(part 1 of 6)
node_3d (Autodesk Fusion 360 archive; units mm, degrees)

design "body_model_corrections" references "pogo_bottomconnect pcb2_", "PCB_forkeypad1_redo", "PCB_forkeypad", "pogo_connect_with_wire", "button"
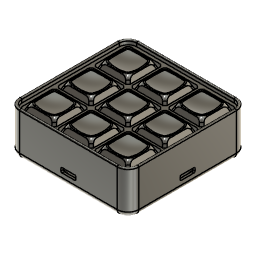
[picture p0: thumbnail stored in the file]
sketch "body" plane through (0, 0, 0) normal (0, 0, 1) x axis (1, 0, 0)
  line L1 (-44, 54) -> (44, 54)
  line L2 (-54, -44) -> (-54, 44)
  line L3 (44, -54) -> (-44, -54)
  line L4 (54, 44) -> (54, -44)
  line L5 (-54, -54) -> (54, 54)
  line L6 (54, -54) -> (-54, 54)
  line L7 (46, 47) -> (-46, 47)
  line L8 (47, -46) -> (47, 46)
  line L9 (-46, -47) -> (46, -47)
  line L10 (-47, 46) -> (-47, -46)
  line L11 (47, -47) -> (-47, 47)
  line L12 (-47, -47) -> (47, 47)
  line L13 (-47.5, 49) -> (47.5, 49)
  line L14 (-51.5, -45) -> (-51.5, 45)
  line L15 (47.5, -49) -> (-47.5, -49)
  line L16 (51.5, 49) -> (51.5, -45)
  line L17 (-51.5, -49) -> (51.5, 49)
  line L18 (51.5, -49) -> (-51.5, 49)
  line L19 (44, -52) -> (-44, -52)
  line L20 (52, 44) -> (52, -44)
  line L21 (-44, 52) -> (44, 52)
  line L22 (-52, -44) -> (-52, 44)
  line L23 (-52, 44) -> (-51.5, 44)
  line L24 (-44.2206, 52) -> (-44.2206, 49)
  line L25 (-51.5, 45) -> (-51.5, 44)
  line L26 (-47.5, 49) -> (-44.2206, 49)
  line L27 (-45, 55) -> (45, 55)
  line L28 (-55, -45) -> (-55, 45)
  line L29 (45, -55) -> (-45, -55)
  line L30 (55, 45) -> (55, -45)
  line L31 (-55, -55) -> (55, 55)
  line L32 (55, -55) -> (-55, 55)
  line L33 (-53, -45) -> (-53, 45)
  line L34 (45, -53) -> (-45, -53)
  line L35 (53, 45) -> (53, -45)
  line L36 (-45, 53) -> (45, 53)
  arc A1 centre (-47.5, 45) radius 4 clockwise from (-51.5, 45) to (-47.5, 49)
  arc A2 centre (47.5, 45) radius 4 clockwise from (47.5, 49) to (51.5, 45)
  arc A3 centre (-47.5, -45) radius 4 clockwise from (-47.5, -49) to (-51.5, -45)
  arc A4 centre (47.5, -45) radius 4 clockwise from (51.5, -45) to (47.5, -49)
  arc A5 centre (-44, 44) radius 10 clockwise from (-54, 44) to (-44, 54)
  arc A6 centre (44, 44) radius 10 clockwise from (44, 54) to (54, 44)
  arc A7 centre (-44, -44) radius 10 clockwise from (-44, -54) to (-54, -44)
  arc A8 centre (44, -44) radius 10 clockwise from (54, -44) to (44, -54)
  arc A9 centre (44, -44) radius 8 clockwise from (52, -44) to (44, -52)
  arc A10 centre (44, 44) radius 8 clockwise from (44, 52) to (52, 44)
  arc A11 centre (-44, 44) radius 8 clockwise from (-52, 44) to (-44, 52)
  arc A12 centre (-44, -44) radius 8 clockwise from (-44, -52) to (-52, -44)
  arc A13 centre (-46, 46) radius 1 clockwise from (-47, 46) to (-46, 47)
  arc A14 centre (46, 46) radius 1 clockwise from (46, 47) to (47, 46)
  arc A15 centre (-46, -46) radius 1 clockwise from (-46, -47) to (-47, -46)
  arc A16 centre (46, -46) radius 1 clockwise from (47, -46) to (46, -47)
  arc A17 centre (45, -45) radius 10 clockwise from (55, -45) to (45, -55)
  arc A18 centre (-45, -45) radius 10 clockwise from (-45, -55) to (-55, -45)
  arc A19 centre (-45, 45) radius 10 clockwise from (-55, 45) to (-45, 55)
  arc A20 centre (45, 45) radius 10 clockwise from (45, 55) to (55, 45)
  arc A21 centre (-45, -45) radius 8 clockwise from (-45, -53) to (-53, -45)
  arc A22 centre (45, -45) radius 8 clockwise from (53, -45) to (45, -53)
  arc A23 centre (45, 45) radius 8 clockwise from (45, 53) to (53, 45)
  arc A24 centre (-45, 45) radius 8 clockwise from (-53, 45) to (-45, 53)
  point P6 (0, 0)
  point P1 (0, 0)
  point P11 (0, 0)
  point P7 (-47, 47)
  point P16 (0, 0)
  point P13 (-51.5, 49)
  point P12 (51.5, 49)
  point P14 (-51.5, -49)
  point P15 (51.5, -49)
  point P3 (-54, 54)
  point P2 (54, 54)
  point P4 (-54, -54)
  point P5 (54, -54)
  point P8 (47, 47)
  point P10 (-47, -47)
  point P9 (47, -47)
  point P65 (-51.5, 44)
  point P66 (-52, 44)
  point P67 (-44.2206, 49)
  point P68 (-44.2206, 52)
  point P73 (0, 0)
  point P72 (55, -55)
  point P71 (-55, -55)
  point P70 (-55, 55)
  point P69 (55, 55)
  horizontal L1
  perpendicular L1 L2
  parallel L1 L3
  parallel L2 L4
  coincident L5 P6
  coincident L6 P6
  coincident P1 P6
  horizontal L7
  perpendicular L7 L8
  parallel L7 L9
  parallel L8 L10
  coincident L11 P11
  coincident L12 P11
  coincident L6 P7
  coincident P1 P11
  horizontal L13
  perpendicular L13 L14
  parallel L13 L15
  parallel L14 L16
  coincident L17 P16
  coincident L18 P16
  coincident P11 P16
  coincident P13 L13
  coincident P13 L14
  tangent L13 A1
  tangent L14 A1
  coincident P12 L13
  tangent L13 A2
  equal A1 A2
  coincident P14 L15
  coincident P14 L14
  tangent L15 A3
  tangent L14 A3
  equal A1 A3
  coincident P15 L15
  coincident P15 L16
  tangent L15 A4
  tangent L16 A4
  coincident P3 L2
  coincident P3 L1
  tangent L2 A5
  tangent L1 A5
  coincident P2 L1
  coincident P2 L4
  tangent L1 A6
  tangent L4 A6
  equal A5 A6
  coincident P4 L3
  coincident P4 L2
  tangent L3 A7
  tangent L2 A7
  equal A5 A7
  coincident P5 L4
  coincident P5 L3
  tangent L4 A8
  tangent L3 A8
  equal A5 A8
  coincident P7 L10
  coincident P7 L7
  tangent L10 A13
  tangent L7 A13
  coincident P8 L7
  coincident P8 L8
  tangent L7 A14
  tangent L8 A14
  equal A13 A14
  coincident P10 L10
  coincident P10 L9
  tangent L10 A15
  tangent L9 A15
  equal A13 A15
  coincident P9 L8
  coincident P9 L9
  tangent L8 A16
  tangent L9 A16
  equal A13 A16
  coincident L14 P65
  coincident L22 P66
  perpendicular L22 L23
  coincident L13 P67
  coincident L21 P68
  perpendicular L21 L24
  horizontal L27
  perpendicular L27 L28
  parallel L27 L29
  parallel L28 L30
  coincident L31 P73
  coincident L32 P73
  coincident P16 P73
  coincident P72 L30
  coincident P72 L29
  tangent L30 A17
  tangent L29 A17
  coincident P71 L28
  coincident P71 L29
  tangent L28 A18
  tangent L29 A18
  equal A17 A18
  coincident P70 L27
  coincident P70 L28
  tangent L27 A19
  tangent L28 A19
  equal A17 A19
  coincident P69 L30
  coincident P69 L27
  tangent L30 A20
  tangent L27 A20
  equal A17 A20
  dimension "d1" distance P4 P5 = 108
  dimension "d2" distance P3 P4 = 108
  dimension "d3" = -2
  dimension "d22" distance P14 P15 = 103
  dimension "d23" distance P13 P14 = 98
  dimension "d24" radius A1 = 4
  dimension "d25" radius A4 = 4
  dimension "d26" radius A5 = 10
  dimension "d40" radius A13 = 1
  dimension "d355" distance P71 P72 = 110
  dimension "d356" distance P70 P71 = 110
  dimension "d357" radius A17 = 10
  dimension "d358" = -2
sketch "Sketch2" plane through (0, 0, 0) normal (0, 0, 1) x axis (1, 0, 0)
  line L1 (0, 0) -> (0, 54)
  line L2 (-15, -87.1142) -> (-15, 54)
  line L3 (15, -87.1142) -> (15, 54)
  line L4 (-15, 49) -> (15, 49)
  line L5 (-15, 45) -> (-15, 49)
  line L6 (15, 45) -> (-15, 45)
  line L7 (15, 49) -> (15, 45)
  line L8 (-15, 45) -> (15, 49)
  line L9 (15, 45) -> (-15, 49)
  line L10 (-22, 52) -> (-22, 47)
  line L11 (15, 49) -> (-15, 49)
  line L12 (-15, 47) -> (-15, 49)
  point P1 (0, 0)
  point P3 (0, 0)
  point P4 (-15, 54)
  point P6 (15, 54)
  point P5 (-15, -87.1142)
  point P7 (15, -87.1142)
  point P12 (0, 47)
  point P15 (-15, 47)
  point P10 (-15, 45)
  point P11 (15, 45)
  point P9 (-15, 49)
  coincident P1 P3
  vertical L1
  symmetric L1 P4 P6
  symmetric L1 P5 P7
  horizontal L4
  perpendicular L4 L5
  parallel L4 L6
  parallel L5 L7
  coincident L8 P12
  coincident L9 P12
  coincident L1 P12
  parallel L5 L10
  midpoint L5 P15
  dimension "d7" = 15
  dimension "d8" distance P10 P11 = 30
  dimension "d9" distance P9 P10 = 4
  dimension "d11" distance L2 L10 = 7
sketch "keyplate" plane through (0, 0, 0) normal (0, 0, 1) x axis (1, 0, 0)
  line L1 (-20, 50) -> (-48, 50)
  line L2 (-18, 20) -> (-18, 48)
  line L3 (-48, 18) -> (-20, 18)
  line L4 (-50, 48) -> (-50, 20)
  line L5 (-44, 52) -> (44, 52)
  line L6 (-52, -44) -> (-52, 44)
  line L7 (44.75, 51.75) -> (-44.75, 51.75)
  line L8 (51.75, -44.75) -> (51.75, 44.75)
  line L9 (-44.75, -51.75) -> (44.75, -51.75)
  line L10 (-51.75, 44.75) -> (-51.75, -44.75)
  line L11 (51.75, -51.75) -> (-51.75, 51.75)
  line L12 (-51.75, -51.75) -> (51.75, 51.75)
  line L13 (-50, 48) -> (-48, 50)
  line L14 (-20, 50) -> (-18, 48)
  line L15 (-20, 18) -> (-18, 20)
  line L16 (-50, 20) -> (-48, 18)
  line L17 (-14, 18) -> (14, 18)
  line L18 (-16, 20) -> (-14, 18)
  line L19 (-16, 48) -> (-16, 20)
  line L20 (-16, 48) -> (-14, 50)
  line L21 (14, 50) -> (-14, 50)
  line L22 (14, 50) -> (16, 48)
  line L23 (14, 18) -> (16, 20)
  line L24 (16, 20) -> (16, 48)
  line L25 (20, 18) -> (48, 18)
  line L26 (18, 20) -> (20, 18)
  line L27 (18, 48) -> (18, 20)
  line L28 (18, 48) -> (20, 50)
  line L29 (48, 50) -> (20, 50)
  line L30 (48, 50) -> (50, 48)
  line L31 (48, 18) -> (50, 20)
  line L32 (50, 20) -> (50, 48)
  line L33 (-48, -16) -> (-20, -16)
  line L34 (-50, -14) -> (-48, -16)
  line L35 (-50, 14) -> (-50, -14)
  line L36 (-50, 14) -> (-48, 16)
  line L37 (-20, 16) -> (-48, 16)
  line L38 (-20, 16) -> (-18, 14)
  line L39 (-20, -16) -> (-18, -14)
  line L40 (-18, -14) -> (-18, 14)
  line L41 (-14, -16) -> (14, -16)
  line L42 (-16, -14) -> (-14, -16)
  line L43 (-16, 14) -> (-16, -14)
  line L44 (-16, 14) -> (-14, 16)
  line L45 (14, 16) -> (-14, 16)
  line L46 (14, 16) -> (16, 14)
  line L47 (14, -16) -> (16, -14)
  line L48 (16, -14) -> (16, 14)
  line L49 (20, -16) -> (48, -16)
  line L50 (18, -14) -> (20, -16)
  line L51 (18, 14) -> (18, -14)
  line L52 (18, 14) -> (20, 16)
  line L53 (48, 16) -> (20, 16)
  line L54 (48, 16) -> (50, 14)
  line L55 (48, -16) -> (50, -14)
  line L56 (50, -14) -> (50, 14)
  line L57 (-48, -50) -> (-20, -50)
  line L58 (-50, -48) -> (-48, -50)
  line L59 (-50, -20) -> (-50, -48)
  line L60 (-50, -20) -> (-48, -18)
  line L61 (-20, -18) -> (-48, -18)
  line L62 (-20, -18) -> (-18, -20)
  line L63 (-20, -50) -> (-18, -48)
  line L64 (-18, -48) -> (-18, -20)
  line L65 (-14, -50) -> (14, -50)
  line L66 (-16, -48) -> (-14, -50)
  line L67 (-16, -20) -> (-16, -48)
  line L68 (-16, -20) -> (-14, -18)
  line L69 (14, -18) -> (-14, -18)
  line L70 (14, -18) -> (16, -20)
  line L71 (14, -50) -> (16, -48)
  line L72 (16, -48) -> (16, -20)
  line L73 (20, -50) -> (48, -50)
  line L74 (18, -48) -> (20, -50)
  line L75 (18, -20) -> (18, -48)
  line L76 (18, -20) -> (20, -18)
  line L77 (48, -18) -> (20, -18)
  line L78 (48, -18) -> (50, -20)
  line L79 (48, -50) -> (50, -48)
  line L80 (50, -48) -> (50, -20)
  line L81 (-16, 20) -> (-18, 20)
  line L82 (-16, 14) -> (-18, 14)
  line L83 (18, 20) -> (16, 20)
  line L84 (18, 14) -> (16, 14)
  line L85 (48, 16) -> (48, 18)
  line L86 (-48, 16) -> (-48, 18)
  line L87 (-48, -16) -> (-48, -18)
  line L88 (-18, -14) -> (-16, -14)
  line L89 (-18, -20) -> (-16, -20)
  line L90 (18, -14) -> (16, -14)
  line L91 (18, -20) -> (16, -20)
  line L92 (48, -18) -> (48, -16)
  line L93 (-44.75, -50) -> (-44.75, -51.75)
  line L94 (44.75, -50) -> (44.75, -51.75)
  line L95 (44.75, 50) -> (44.75, 51.75)
  line L96 (-44.75, 50) -> (-44.75, 51.75)
  line L97 (-14, -50) -> (-20, -50)
  line L98 (20, -50) -> (14, -50)
  line L99 (-14, 50) -> (-20, 50)
  line L100 (20, 50) -> (14, 50)
  line L101 (18, -32) -> (16, -32)
  line L102 (13.5, -32) -> (17, -32)
  line L103 (20.5, -32) -> (17, -32)
  line L104 (13.5, 50) -> (13.5, -50)
  line L105 (20.5, 50) -> (20.5, -50)
  line L106 (0, -4) -> (0, 0)
  line L107 (-20.5, 50) -> (-20.5, -50)
  line L108 (-13.5, 50) -> (-13.5, -50)
  line L109 (-44.75, -52.95) -> (44.75, -52.95)
  line L110 (52.95, -44.75) -> (52.95, 44.75)
  line L111 (44.75, 52.95) -> (-44.75, 52.95)
  line L112 (-52.95, 44.75) -> (-52.95, -44.75)
  arc A1 centre (-44.75, 44.75) radius 7 clockwise from (-51.75, 44.75) to (-44.75, 51.75)
  arc A2 centre (44.75, 44.75) radius 7 clockwise from (44.75, 51.75) to (51.75, 44.75)
  arc A3 centre (44.75, -44.75) radius 7 clockwise from (51.75, -44.75) to (44.75, -51.75)
  arc A4 centre (-44.75, -44.75) radius 7 clockwise from (-44.75, -51.75) to (-51.75, -44.75)
  arc A5 centre (-44.75, -44.75) radius 8.2 clockwise from (-44.75, -52.95) to (-52.95, -44.75)
  arc A6 centre (44.75, -44.75) radius 8.2 clockwise from (52.95, -44.75) to (44.75, -52.95)
  arc A7 centre (44.75, 44.75) radius 8.2 clockwise from (44.75, 52.95) to (52.95, 44.75)
  arc A8 centre (-44.75, 44.75) radius 8.2 clockwise from (-52.95, 44.75) to (-44.75, 52.95)
  point P13 (0, 0)
  point P1 (0, 0)
  point P9 (-51.75, 51.75)
  point P10 (51.75, 51.75)
  point P11 (51.75, -51.75)
  point P12 (-51.75, -51.75)
  point P2 (-50, 50)
  point P3 (-18, 50)
  point P4 (-18, 18)
  point P5 (-50, 18)
  point P99 (-44.75, -50)
  point P100 (44.75, -50)
  point P101 (44.75, 50)
  point P102 (-44.75, 50)
  point P103 (16, -32)
  point P104 (18, -32)
  point P105 (17, -32)
  point P108 (13.5, 50)
  point P106 (13.5, -32)
  point P110 (20.5, 50)
  point P107 (20.5, -32)
  point P112 (0, 0)
  point P117 (-13.5, 50)
  point P109 (13.5, -50)
  point P116 (-13.5, -50)
  point P115 (-20.5, 50)
  point P111 (20.5, -50)
  point P114 (-20.5, -50)
  point P27 (-48, 50)
  point P28 (-50, 48)
  point P29 (-18, 48)
  point P30 (-20, 50)
  point P31 (-18, 20)
  point P32 (-20, 18)
  point P33 (-48, 18)
  point P34 (-50, 20)
  horizontal L1
  vertical L2
  horizontal L3
  vertical L4
  horizontal L7
  perpendicular L7 L8
  parallel L7 L9
  parallel L8 L10
  coincident L11 P13
  coincident L12 P13
  coincident P1 P13
  coincident P9 L7
  coincident P9 L10
  tangent L7 A1
  tangent L10 A1
  coincident P10 L7
  coincident P10 L8
  tangent L7 A2
  tangent L8 A2
  equal A1 A2
  coincident P11 L9
  coincident P11 L8
  tangent L9 A3
  tangent L8 A3
  equal A1 A3
  coincident P12 L9
  coincident P12 L10
  tangent L9 A4
  tangent L10 A4
  equal A1 A4
  coincident P2 L1
  coincident P2 L4
  coincident P3 L2
  coincident P3 L1
  coincident P4 L2
  coincident P4 L3
  coincident P5 L3
  coincident P5 L4
  coincident L57 P99
  perpendicular L57 L93
  coincident L73 P100
  perpendicular L73 L94
  coincident L29 P101
  perpendicular L29 L95
  coincident L1 P102
  perpendicular L1 L96
  coincident L72 P103
  coincident L75 P104
  perpendicular L75 L101
  midpoint L101 P105
  perpendicular L75 L102
  perpendicular L75 L103
  coincident L21 P108
  perpendicular L21 L104
  coincident P106 L104
  coincident L29 P110
  perpendicular L29 L105
  coincident P107 L105
  coincident P1 P112
  perpendicular L41 L106
  symmetric P108 L106 P117
  symmetric P109 L106 P116
  symmetric P110 L106 P115
  symmetric P111 L106 P114
  dimension "d12" distance P2 P3 = 32
  dimension "d13" distance P2 P5 = 32
  dimension "d14" distance L1 L5 = 2
  dimension "d15" distance L4 L6 = 2
  dimension "d20" distance P11 P12 = 103.5
  dimension "d21" distance P10 P11 = 103.5
  dimension "d27" radius A1 = 7
  dimension "d28" distance P2 P27 = 2
  dimension "d29" distance P2 P28 = 2 (= "d28")
  dimension "d30" distance P3 P29 = 2
  dimension "d31" distance P3 P30 = 2 (= "d30")
  dimension "d32" distance P4 P31 = 2
  dimension "d33" distance P4 P32 = 2 (= "d32")
  dimension "d34" distance P5 P33 = 2
  dimension "d35" distance P5 P34 = 2 (= "d34")
  dimension "d266" distance P105 P106 = 3.5
  dimension "d267" distance P105 P107 = 3.5
  dimension "d364" = -1.2
  dimension "d38" R-Pattern1-uDistance = 34
  dimension "d39" R-Pattern1-vDistance = -34
sketch "slot" plane through (0, 0, 0) normal (0, 0, 1) x axis (1, 0, 0)
  line L1 (0, 54) -> (0, 0)
  line L2 (20, 54) -> (20, 0)
  line L3 (-20, 54) -> (-20, 0)
  line L4 (20, 49) -> (-20, 49)
  line L5 (-15, 49) -> (-15, 47)
  line L6 (15, 49) -> (15, 47)
  line L7 (-22, 47) -> (-15, 47)
  line L8 (22, 47) -> (15, 47)
  line L9 (-20, 52) -> (-20, 49)
  line L10 (20, 52) -> (20, 49)
  line L11 (20, 52) -> (20, 49)
  line L12 (-3.25, 49) -> (-3.25, 50.9)
  line L13 (3.25, 49) -> (3.25, 50.9)
  line L14 (-22, 47) -> (-22, 52)
  line L15 (22, 47) -> (22, 52)
  line L16 (22, 52) -> (-22, 52)
  line L17 (15, 47) -> (-15, 47)
  line L18 (-3.25, 50.9) -> (3.25, 50.9)
  line L19 (22, 50.9) -> (3.25, 50.9)
  line L20 (-22, 50.9) -> (-3.25, 50.9)
  line L21 (-15, 49.5) -> (-15, 49)
  point P8 (-20, 49)
  point P9 (20, 49)
  point P11 (-15, 49)
  point P13 (15, 49)
  point P14 (-20, 52)
  point P15 (20, 52)
  point P16 (20, 49)
  point P18 (-3.25, 49)
  point P20 (3.25, 49)
  point P25 (22, 50.9)
  point P26 (-22, 50.9)
  point P17 (-3.25, 50.9)
  point P19 (3.25, 50.9)
  vertical L1
  coincident L3 P8
  coincident L2 P9
  perpendicular L2 L4
  coincident L4 P11
  perpendicular L4 L5
  coincident L4 P13
  perpendicular L4 L6
  horizontal L7
  coincident L3 P14
  coincident L2 P15
  symmetric L1 P8 P16
  symmetric L1 P14 P15
  coincident L4 P18
  coincident L4 P20
  perpendicular L7 L14
  perpendicular L8 L15
  perpendicular L15 L16
  perpendicular L6 L17
  coincident L15 P25
  perpendicular L15 L19
  coincident L14 P26
  perpendicular L14 L20
  perpendicular L4 L21
  dimension "d48" distance L1 L5 = 15
  dimension "d49" distance L1 L6 = 15
  dimension "d50" distance L1 L9 = 20
  dimension "d51" distance L1 L10 = 20
  dimension "d52" distance P8 P14 = 3
  dimension "d55" distance L1 L12 = 3.25
  dimension "d56" distance L1 L13 = 3.25
  dimension "d57" distance P17 P18 = 1.9
  dimension "d58" distance P19 P20 = 1.9
  dimension "d63" distance L9 L14 = 2
  dimension "d64" distance L10 L15 = 2
extrude "Extrude7" new body sketch "body" profile of L1 L2 L3 L4 L22 L19 L20 L21 L7 L8 L9 L10 A1 A5 A11 A6 A10 A7 A12 A8 A9 A13 A14 A15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 against normal blind 28
shell "Shell2" innerThickness 2
extrude "Extrude8" sketch "body" profile of L22 L19 L20 L21 L7 L8 L9 L10 A1 A11 A10 A12 A9 A13 A14 A15 A16 L23 L24 L25 L26 L34 A22 L36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 blind 19.2
fillet "Fillet2" radius 5
extrude "Extrude15" cut sketch "slot" profile of L4 L5 L6 L9 L10 L11 L12 L13 L17 L18 L19 L20 against normal blind 26
extrude "Extrude16" sketch "slot" profile of L4 L9 L10 L11 L12 L13 L19 L20 blind 3.5
sketch "holder" plane through (0, 0, 0) normal (0, 0, 1) x axis (1, 0, 0)
  line L1 (12, 16) -> (-12, 16)
  line L2 (16, -12) -> (16, 12)
  line L3 (-12, -16) -> (12, -16)
  line L4 (-16, 12) -> (-16, -12)
  line L5 (16, -16) -> (-16, 16)
  line L6 (-16, -16) -> (16, 16)
  line L7 (-12, -16.15) -> (12, -16.15)
  line L8 (16.15, -12) -> (16.15, 12)
  line L9 (12, 16.15) -> (-12, 16.15)
  line L10 (-16.15, 12) -> (-16.15, -12)
  line L11 (-12, -17.8) -> (12, -17.8)
  line L12 (17.8, -12) -> (17.8, 12)
  line L13 (12, 17.8) -> (-12, 17.8)
  line L14 (-17.8, 12) -> (-17.8, -12)
  line L15 (-12, -14.65) -> (12, -14.65)
  line L16 (14.65, -12) -> (14.65, 12)
  line L17 (12, 14.65) -> (-12, 14.65)
  line L18 (-14.65, 12) -> (-14.65, -12)
  line L19 (0, -14.65) -> (0, -17.8)
  line L20 (3.25, -14.65) -> (3.25, -17.8)
  line L21 (-3.25, -14.65) -> (-3.25, -17.8)
  line L22 (14.65, -3.25) -> (17.8, -3.25)
  line L23 (14.65, 3.25) -> (17.8, 3.25)
  line L24 (3.25, 14.65) -> (3.25, 17.8)
  line L25 (-3.25, 14.65) -> (-3.25, 17.8)
  line L26 (-14.65, 3.25) -> (-17.8, 3.25)
  line L27 (-14.65, -3.25) -> (-17.8, -3.25)
  line L28 (45, 53) -> (-45, 53)
  line L29 (53, -45) -> (53, 45)
  line L30 (-45, -53) -> (45, -53)
  line L31 (-53, 45) -> (-53, -45)
  line L32 (-45, 55) -> (45, 55)
  line L33 (-55, -45) -> (-55, 45)
  line L34 (45, -55) -> (-45, -55)
  line L35 (55, 45) -> (55, -45)
  arc A1 centre (12, 12) radius 4 clockwise from (12, 16) to (16, 12)
  arc A2 centre (-12, 12) radius 4 clockwise from (-16, 12) to (-12, 16)
  arc A3 centre (-12, -12) radius 4 clockwise from (-12, -16) to (-16, -12)
  arc A4 centre (12, -12) radius 4 clockwise from (16, -12) to (12, -16)
  arc A5 centre (-12, -12) radius 4.15 clockwise from (-12, -16.15) to (-16.15, -12)
  arc A6 centre (12, -12) radius 4.15 clockwise from (16.15, -12) to (12, -16.15)
  arc A7 centre (12, 12) radius 4.15 clockwise from (12, 16.15) to (16.15, 12)
  arc A8 centre (-12, 12) radius 4.15 clockwise from (-16.15, 12) to (-12, 16.15)
  arc A9 centre (-12, -12) radius 5.8 clockwise from (-12, -17.8) to (-17.8, -12)
  arc A10 centre (12, -12) radius 5.8 clockwise from (17.8, -12) to (12, -17.8)
  arc A11 centre (12, 12) radius 5.8 clockwise from (12, 17.8) to (17.8, 12)
  arc A12 centre (-12, 12) radius 5.8 clockwise from (-17.8, 12) to (-12, 17.8)
  arc A13 centre (-12, -12) radius 2.65 clockwise from (-12, -14.65) to (-14.65, -12)
  arc A14 centre (12, -12) radius 2.65 clockwise from (14.65, -12) to (12, -14.65)
  arc A15 centre (12, 12) radius 2.65 clockwise from (12, 14.65) to (14.65, 12)
  arc A16 centre (-12, 12) radius 2.65 clockwise from (-14.65, 12) to (-12, 14.65)
  arc A17 centre (45, 45) radius 8 clockwise from (45, 53) to (53, 45)
  arc A18 centre (45, -45) radius 8 clockwise from (53, -45) to (45, -53)
  arc A19 centre (-45, -45) radius 8 clockwise from (-45, -53) to (-53, -45)
  arc A20 centre (-45, 45) radius 8 clockwise from (-53, 45) to (-45, 53)
  arc A21 centre (45, 45) radius 10 clockwise from (45, 55) to (55, 45)
  arc A22 centre (-45, 45) radius 10 clockwise from (-55, 45) to (-45, 55)
  arc A23 centre (-45, -45) radius 10 clockwise from (-45, -55) to (-55, -45)
  arc A24 centre (45, -45) radius 10 clockwise from (55, -45) to (45, -55)
  point P6 (0, 0)
  point P1 (0, 0)
  point P3 (16, 16)
  point P2 (-16, 16)
  point P5 (-16, -16)
  point P4 (16, -16)
  point P55 (0, -17.8)
  point P56 (0, -14.65)
  horizontal L1
  perpendicular L1 L2
  parallel L1 L3
  parallel L2 L4
  coincident L5 P6
  coincident L6 P6
  coincident P1 P6
  coincident P3 L2
  coincident P3 L1
  tangent L2 A1
  tangent L1 A1
  coincident P2 L4
  coincident P2 L1
  tangent L4 A2
  tangent L1 A2
  coincident P5 L3
  coincident P5 L4
  tangent L3 A3
  tangent L4 A3
  equal A2 A3
  coincident P4 L3
  coincident P4 L2
  tangent L3 A4
  tangent L2 A4
  equal A2 A4
  concentric A3 A5
  concentric A4 A6
  concentric A1 A7
  concentric A2 A8
  tangent A5 L10
  tangent L8 A7
  tangent A5 L7
  tangent A6 L8
  tangent L7 A6
  tangent L9 A8
  tangent A7 L9
  tangent A8 L10
  midpoint L11 P55
  midpoint L15 P56
  perpendicular L15 L19
  dimension "d101" distance P4 P5 = 32
  dimension "d102" distance P3 P4 = 32
  dimension "d103" radius A1 = 4
  dimension "d104" radius A2 = 4
  dimension "d106" = -1.65
  dimension "d107" = 1.35
  dimension "d134" = 3.25
  dimension "d135" = -3.25
  dimension "d137" C-Pattern1-Angle = 360
sketch "close" plane through (0, 0, 0) normal (0, 1, 0) x axis (1, 0, 0)
  line L1 (3.25, 22.5) -> (3.25, 26)
  line L2 (20, 22.5) -> (3.25, 22.5)
  line L3 (20, 6.8) -> (20, 22.5)
  line L4 (-20, 6.8) -> (20, 6.8)
  line L5 (-20, 22.5) -> (-20, 6.8)
  line L6 (-3.25, 22.5) -> (-20, 22.5)
  line L7 (-3.25, 26) -> (-3.25, 22.5)
  line L8 (3.25, 26) -> (-3.25, 26)
  line L9 (-3, 17.75) -> (3, 17.75)
  line L10 (-6, 13.25) -> (-6, 14.75)
  line L11 (3, 10.25) -> (-3, 10.25)
  line L12 (6, 14.75) -> (6, 13.25)
  line L13 (-6, 10.25) -> (6, 17.75)
  line L14 (6, 10.25) -> (-6, 17.75)
  arc A1 centre (-3, 13.25) radius 3 clockwise from (-3, 10.25) to (-6, 13.25)
  arc A2 centre (-3, 14.75) radius 3 clockwise from (-6, 14.75) to (-3, 17.75)
  arc A3 centre (3, 14.75) radius 3 clockwise from (3, 17.75) to (6, 14.75)
  arc A4 centre (3, 13.25) radius 3 clockwise from (6, 13.25) to (3, 10.25)
  point P14 (0, 14)
  point P12 (-6, 10.25)
  point P11 (-6, 17.75)
  point P10 (6, 17.75)
  point P13 (6, 10.25)
  horizontal L9
  perpendicular L9 L10
  parallel L9 L11
  parallel L10 L12
  coincident L13 P14
  coincident L14 P14
  coincident P12 L11
  coincident P12 L10
  tangent L11 A1
  tangent L10 A1
  coincident P11 L10
  coincident P11 L9
  tangent L10 A2
  tangent L9 A2
  equal A1 A2
  coincident P10 L9
  coincident P10 L12
  tangent L9 A3
  tangent L12 A3
  equal A1 A3
  coincident P13 L12
  coincident P13 L11
  tangent L12 A4
  tangent L11 A4
  equal A1 A4
  dimension "d249" distance P10 P13 = 7.5
  dimension "d250" distance P10 P11 = 12
  dimension "d251" radius A1 = 3
extrude "Extrude17" sketch "close" profile of L1 L2 L3 L4 L5 L6 L7 L8 to an object bodies "close"
combine "Combine2"
offset_faces "OffsetFaces5" distance -0.15
offset_faces "OffsetFaces6" distance -0.15
offset_faces "OffsetFaces7" distance -0.15
offset_faces "OffsetFaces8" distance 0.15
offset_faces "OffsetFaces9" distance -1
offset_faces "OffsetFaces10" distance 0.2
offset_faces "OffsetFaces24" distance -0.15
sketch "pogpslot" plane through (0, 50.9, 0) normal (0, -1, 0) x axis (1, 0, 0)
  line L1 (3.25, -22.5) -> (3.25, -26)
  line L2 (20, -22.5) -> (3.25, -22.5)
  line L3 (20, -6.8) -> (20, -22.5)
  line L4 (-20, -6.8) -> (20, -6.8)
  line L5 (-20, -22.5) -> (-20, -6.8)
  line L6 (-3.25, -22.5) -> (-20, -22.5)
  line L7 (-3.25, -26) -> (-3.25, -22.5)
  line L8 (3.25, -26) -> (-3.25, -26)
  line L9 (15, -22.5) -> (3.25, -22.5)
  line L10 (-3.25, -22.5) -> (-15, -22.5)
  line L11 (0, -26) -> (0, -6.8)
  line L12 (20, -22) -> (-20, -22)
  line L13 (-15, -27.8) -> (-15, -6.8)
  line L14 (10, -22) -> (-10, -22)
  line L15 (-10, -12) -> (10, -12)
  line L16 (-5.92, -19.19) -> (5.92, -19.19)
  line L17 (-6.92, -15.81) -> (-6.92, -18.19)
  line L18 (5.92, -14.81) -> (-5.92, -14.81)
  line L19 (6.92, -18.19) -> (6.92, -15.81)
  line L20 (-6.92, -14.81) -> (6.92, -19.19)
  line L21 (6.92, -14.81) -> (-6.92, -19.19)
  arc A1 centre (10, -17) radius 5 clockwise from (10, -12) to (15, -17)
  arc A2 centre (10, -17) radius 5 clockwise from (15, -17) to (10, -22)
  arc A3 centre (-10, -17) radius 5 clockwise from (-15, -17) to (-10, -12)
  arc A4 centre (-10, -17) radius 5 clockwise from (-10, -22) to (-15, -17)
  arc A5 centre (-5.92, -15.81) radius 1 clockwise from (-6.92, -15.81) to (-5.92, -14.81)
  arc A6 centre (-5.92, -18.19) radius 1 clockwise from (-5.92, -19.19) to (-6.92, -18.19)
  arc A7 centre (5.92, -18.19) radius 1 clockwise from (6.92, -18.19) to (5.92, -19.19)
  arc A8 centre (5.92, -15.81) radius 1 clockwise from (5.92, -14.81) to (6.92, -15.81)
  point P14 (0, -6.8)
  point P15 (0, -26)
  point P16 (-20, -22)
  point P17 (20, -22)
  point P18 (-15, -6.8)
  point P20 (-15, -22)
  point P21 (15, -22)
  point P24 (15, -17)
  point P26 (15, -17)
  point P22 (-15, -12)
  point P30 (-15, -17)
  point P33 (-15, -17)
  point P39 (0, -17)
  point P37 (-6.92, -14.81)
  point P36 (-6.92, -19.19)
  point P35 (6.92, -19.19)
  point P38 (6.92, -14.81)
  midpoint L4 P14
  midpoint L8 P15
  coincident L5 P16
  coincident L3 P17
  perpendicular L3 L12
  coincident L4 P18
  perpendicular L4 L13
  horizontal L14
  horizontal L15
  coincident L13 P20
  coincident L12 P20
  tangent L15 A1
  coincident P21 L14
  tangent L14 A2
  equal A1 A2
  coincident P24 P26
  coincident P22 L15
  tangent L15 A3
  equal A1 A3
  coincident P20 L14
  tangent L14 A4
  equal A1 A4
  coincident P30 P33
  horizontal L16
  perpendicular L16 L17
  parallel L16 L18
  parallel L17 L19
  coincident L20 P39
  coincident L21 P39
  coincident L11 P39
  coincident P37 L17
  coincident P37 L18
  tangent L17 A5
  tangent L18 A5
  coincident P36 L17
  coincident P36 L16
  tangent L17 A6
  tangent L16 A6
  equal A5 A6
  coincident P35 L16
  coincident P35 L19
  tangent L16 A7
  tangent L19 A7
  equal A5 A7
  coincident P38 L18
  coincident P38 L19
  tangent L18 A8
  tangent L19 A8
  dimension "d138" distance L6 L12 = 0.5
  dimension "d139" distance L11 L13 = 15
  dimension "d140" distance P20 P21 = 30
  dimension "d142" radius A1 = 5
  dimension "d143" distance L14 L15 = 10
  dimension "d144" distance P37 P38 = 13.84
  dimension "d145" distance P36 P37 = 4.38
  dimension "d146" radius A5 = 1
  dimension "d147" radius A8 = 1
extrude "Extrude18" cut sketch "pogpslot" profile of L16 L17 L18 L19 A5 A6 A7 A8 against normal blind 15
extrude "Extrude19" cut sketch "pogpslot" profile of L14 L15 A1 A2 A3 A4 L16 L17 L18 L19 A5 A6 A7 A8 against normal blind 2
extrude "Extrude20" sketch "body" profile of L22 L21 A1 A11 L23 L24 L25 L26 blind 3.5 bodies "pcbholdup"
component_insert "Component Insert1"
position "Position1"
extrude "Extrude21" new body sketch "keyplate" profile of L1 L2 L3 L4 L7 L8 L9 L10 A1 A2 A3 A4 L13 L14 L15 L16 L17 L18 L19 L20 L21 L22 L23 L24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 against normal blind 5.35
extrude "Extrude22" sketch "keyplate" profile of L1 L7 L9 L21 L29 L57 L65 L73 L93 L94 L95 L96 L97 L98 L99 L100 blind -2 bodies "keyplate"
offset_faces "OffsetFaces11" distance 12
external_derived "ExternalDerived1"
derived_instance "DerivedInstance1"
position "Position2"
combine "Combine4"
sketch "Sketch11" plane through (0, 0, 0) normal (0, 1, 0) x axis (1, 0, 0)
  line L1 (15, 26) -> (15, 6.8)
  line L2 (46, 26) -> (15, 26)
  line L3 (46, 6.8) -> (46, 26)
  line L4 (15, 6.8) -> (46, 6.8)
  line L5 (-15, 6.8) -> (-15, 26)
  line L6 (-46, 6.8) -> (-15, 6.8)
  line L7 (-46, 26) -> (-46, 6.8)
  line L8 (-15, 26) -> (-46, 26)
  line L9 (-30.5, 26) -> (-30.5, 6.8)
  line L10 (-46, 16.4) -> (-15, 16.4)
  line L11 (15, 16.4) -> (-15, 16.4)
  line L12 (0, 7) -> (0, 16.4)
  circle C1 centre (-30.5, 16.4) radius 5.1
  circle C2 centre (30.5, 16.4) radius 5.1
  point P10 (-30.5, 6.8)
  point P11 (-30.5, 26)
  point P12 (-15, 16.4)
  point P13 (-46, 16.4)
  point P14 (-30.5, 16.4)
  point P15 (15, 16.4)
  point P16 (0, 16.4)
  midpoint L6 P10
  midpoint L8 P11
  midpoint L5 P12
  midpoint L7 P13
  midpoint L9 P14
  midpoint L1 P15
  midpoint L11 P16
  perpendicular L11 L12
  symmetric C1 L12 C2
  dimension "d161" diameter C1 = 10.2
extrude "Extrude23" sketch "Sketch11" profile of C1 C2 blind 6.5
rectangular_pattern "00000000-0000-0000-0000-000000000000" uSpaceDistance -68 vSpaceDistance 34
sketch "Sketch12" plane through (0, 0, 0) normal (0, 0, 1) x axis (-1, 0, 0)
  line L1 (-20, 18) -> (-18, 20)
  line L2 (-48, 18) -> (-20, 18)
  line L3 (-50, 20) -> (-48, 18)
  line L4 (-50, 48) -> (-50, 20)
  line L5 (-48, 50) -> (-50, 48)
  line L6 (-20, 50) -> (-48, 50)
  line L7 (-18, 48) -> (-20, 50)
  line L8 (-18, 20) -> (-18, 48)
  line L9 (14, -16) -> (16, -14)
  line L10 (-14, -16) -> (14, -16)
  line L11 (-16, -14) -> (-14, -16)
  line L12 (-16, 14) -> (-16, -14)
  line L13 (-14, 16) -> (-16, 14)
  line L14 (14, 16) -> (-14, 16)
  line L15 (16, 14) -> (14, 16)
  line L16 (16, -14) -> (16, 14)
  line L17 (-20, -16) -> (-18, -14)
  line L18 (-48, -16) -> (-20, -16)
  line L19 (-50, -14) -> (-48, -16)
  line L20 (-50, 14) -> (-50, -14)
  line L21 (-48, 16) -> (-50, 14)
  line L22 (-20, 16) -> (-48, 16)
  line L23 (-18, 14) -> (-20, 16)
  line L24 (-18, -14) -> (-18, 14)
  line L25 (14, 18) -> (16, 20)
  line L26 (-14, 18) -> (14, 18)
  line L27 (-16, 20) -> (-14, 18)
  line L28 (-16, 48) -> (-16, 20)
  line L29 (-14, 50) -> (-16, 48)
  line L30 (14, 50) -> (-14, 50)
  line L31 (16, 48) -> (14, 50)
  line L32 (16, 20) -> (16, 48)
  line L33 (-20, -50) -> (-18, -48)
  line L34 (-48, -50) -> (-20, -50)
  line L35 (-50, -48) -> (-48, -50)
  line L36 (-50, -20) -> (-50, -48)
  line L37 (-48, -18) -> (-50, -20)
  line L38 (-20, -18) -> (-48, -18)
  line L39 (-18, -20) -> (-20, -18)
  line L40 (-18, -48) -> (-18, -20)
  line L41 (14, -50) -> (16, -48)
  line L42 (-14, -50) -> (14, -50)
  line L43 (-16, -48) -> (-14, -50)
  line L44 (-16, -20) -> (-16, -48)
  line L45 (-14, -18) -> (-16, -20)
  line L46 (14, -18) -> (-14, -18)
  line L47 (16, -20) -> (14, -18)
  line L48 (16, -48) -> (16, -20)
  line L49 (18, -48) -> (20, -50)
  line L50 (18, -20) -> (18, -48)
  line L51 (20, -18) -> (18, -20)
  line L52 (48, -18) -> (20, -18)
  line L53 (50, -20) -> (48, -18)
  line L54 (50, -48) -> (50, -20)
  line L55 (48, -50) -> (50, -48)
  line L56 (20, -50) -> (48, -50)
  line L57 (48, 18) -> (50, 20)
  line L58 (20, 18) -> (48, 18)
  line L59 (18, 20) -> (20, 18)
  line L60 (18, 48) -> (18, 20)
  line L61 (20, 50) -> (18, 48)
  line L62 (48, 50) -> (20, 50)
  line L63 (50, 48) -> (48, 50)
  line L64 (50, 20) -> (50, 48)
  line L65 (48, -16) -> (50, -14)
  line L66 (20, -16) -> (48, -16)
  line L67 (18, -14) -> (20, -16)
  line L68 (18, 14) -> (18, -14)
  line L69 (20, 16) -> (18, 14)
  line L70 (48, 16) -> (20, 16)
  line L71 (50, 14) -> (48, 16)
  line L72 (50, -14) -> (50, 14)
  line L73 (51.75, 44.75) -> (51.75, -44.75)
  line L74 (-44.75, 51.75) -> (44.75, 51.75)
  line L75 (-51.75, -44.75) -> (-51.75, 44.75)
  line L76 (44.75, -51.75) -> (-44.75, -51.75)
  arc A1 centre (44.75, -44.75) radius 7 clockwise from (51.75, -44.75) to (44.75, -51.75)
  arc A2 centre (44.75, 44.75) radius 7 clockwise from (44.75, 51.75) to (51.75, 44.75)
  arc A3 centre (-44.75, 44.75) radius 7 clockwise from (-51.75, 44.75) to (-44.75, 51.75)
  arc A4 centre (-44.75, -44.75) radius 7 clockwise from (-44.75, -51.75) to (-51.75, -44.75)
sketch "Sketch13" plane through (0, 0, 0) normal (0, 0, 1) x axis (-1, 0, 0)
  line L1 (-20, 18) -> (-18, 20)
  line L2 (-48, 18) -> (-20, 18)
  line L3 (-50, 20) -> (-48, 18)
  line L4 (-50, 48) -> (-50, 20)
  line L5 (-48, 50) -> (-50, 48)
  line L6 (-20, 50) -> (-48, 50)
  line L7 (-18, 48) -> (-20, 50)
  line L8 (-18, 20) -> (-18, 48)
  line L9 (14, -16) -> (16, -14)
  line L10 (-14, -16) -> (14, -16)
  line L11 (-16, -14) -> (-14, -16)
  line L12 (-16, 14) -> (-16, -14)
  line L13 (-14, 16) -> (-16, 14)
  line L14 (14, 16) -> (-14, 16)
  line L15 (16, 14) -> (14, 16)
  line L16 (16, -14) -> (16, 14)
  line L17 (-20, -16) -> (-18, -14)
  line L18 (-48, -16) -> (-20, -16)
  line L19 (-50, -14) -> (-48, -16)
  line L20 (-50, 14) -> (-50, -14)
  line L21 (-48, 16) -> (-50, 14)
  line L22 (-20, 16) -> (-48, 16)
  line L23 (-18, 14) -> (-20, 16)
  line L24 (-18, -14) -> (-18, 14)
  line L25 (14, 18) -> (16, 20)
  line L26 (-14, 18) -> (14, 18)
  line L27 (-16, 20) -> (-14, 18)
  line L28 (-16, 48) -> (-16, 20)
  line L29 (-14, 50) -> (-16, 48)
  line L30 (14, 50) -> (-14, 50)
  line L31 (16, 48) -> (14, 50)
  line L32 (16, 20) -> (16, 48)
  line L33 (-20, -50) -> (-18, -48)
  line L34 (-48, -50) -> (-20, -50)
  line L35 (-50, -48) -> (-48, -50)
  line L36 (-50, -20) -> (-50, -48)
  line L37 (-48, -18) -> (-50, -20)
  line L38 (-20, -18) -> (-48, -18)
  line L39 (-18, -20) -> (-20, -18)
  line L40 (-18, -48) -> (-18, -20)
  line L41 (14, -50) -> (16, -48)
  line L42 (-14, -50) -> (14, -50)
  line L43 (-16, -48) -> (-14, -50)
  line L44 (-16, -20) -> (-16, -48)
  line L45 (-14, -18) -> (-16, -20)
  line L46 (14, -18) -> (-14, -18)
  line L47 (16, -20) -> (14, -18)
  line L48 (16, -48) -> (16, -20)
  line L49 (18, -48) -> (20, -50)
  line L50 (18, -20) -> (18, -48)
  line L51 (20, -18) -> (18, -20)
  line L52 (48, -18) -> (20, -18)
  line L53 (50, -20) -> (48, -18)
  line L54 (50, -48) -> (50, -20)
  line L55 (48, -50) -> (50, -48)
  line L56 (20, -50) -> (48, -50)
  line L57 (48, 18) -> (50, 20)
  line L58 (20, 18) -> (48, 18)
  line L59 (18, 20) -> (20, 18)
  line L60 (18, 48) -> (18, 20)
  line L61 (20, 50) -> (18, 48)
  line L62 (48, 50) -> (20, 50)
  line L63 (50, 48) -> (48, 50)
  line L64 (50, 20) -> (50, 48)
  line L65 (48, -16) -> (50, -14)
  line L66 (20, -16) -> (48, -16)
  line L67 (18, -14) -> (20, -16)
  line L68 (18, 14) -> (18, -14)
  line L69 (20, 16) -> (18, 14)
  line L70 (48, 16) -> (20, 16)
  line L71 (50, 14) -> (48, 16)
  line L72 (50, -14) -> (50, 14)
  line L73 (51.75, 44.75) -> (51.75, -44.75)
  line L74 (-44.75, 51.75) -> (44.75, 51.75)
  line L75 (-51.75, -44.75) -> (-51.75, 44.75)
  line L76 (44.75, -51.75) -> (-44.75, -51.75)
  arc A1 centre (44.75, -44.75) radius 7 clockwise from (51.75, -44.75) to (44.75, -51.75)
  arc A2 centre (44.75, 44.75) radius 7 clockwise from (44.75, 51.75) to (51.75, 44.75)
  arc A3 centre (-44.75, 44.75) radius 7 clockwise from (-51.75, 44.75) to (-44.75, 51.75)
  arc A4 centre (-44.75, -44.75) radius 7 clockwise from (-44.75, -51.75) to (-51.75, -44.75)
component_insert "Component Insert4"
sketch "mounts" plane through (0, 0, -26) normal (0, 0, 1) x axis (-1, 0, 0)
  line L1 (-3.25, -49) -> (-15, -49)
  line L2 (-3.25, -50.9) -> (-3.25, -49)
  line L3 (3.25, -50.9) -> (-3.25, -50.9)
  line L4 (3.25, -49) -> (3.25, -50.9)
  line L5 (15, -49) -> (3.25, -49)
  line L6 (15, -47) -> (15, -49)
  line L7 (46, -47) -> (15, -47)
  line L8 (47, 46) -> (47, -46)
  line L9 (-46, 47) -> (46, 47)
  line L10 (-47, -46) -> (-47, 46)
  line L11 (-15, -47) -> (-46, -47)
  line L12 (-15, -49) -> (-15, -47)
  line L13 (14.53, 37.19) -> (18.83, 37.19)
  line L14 (12.03, 30.39) -> (12.03, 34.69)
  line L15 (18.83, 27.89) -> (14.53, 27.89)
  line L16 (21.33, 34.69) -> (21.33, 30.39)
  line L17 (12.03, 27.89) -> (21.33, 37.19)
  line L18 (21.33, 27.89) -> (12.03, 37.19)
  line L19 (-14.19, 37.19) -> (-18.49, 37.19)
  line L20 (-11.69, 30.39) -> (-11.69, 34.69)
  line L21 (-18.49, 27.89) -> (-14.19, 27.89)
  line L22 (-20.99, 34.69) -> (-20.99, 30.39)
  line L23 (-11.69, 27.89) -> (-20.99, 37.19)
  line L24 (-20.99, 27.89) -> (-11.69, 37.19)
  line L25 (18.83, -28.215) -> (14.53, -28.215)
  line L26 (21.33, -35.015) -> (21.33, -30.715)
  line L27 (14.53, -37.515) -> (18.83, -37.515)
  line L28 (12.03, -30.715) -> (12.03, -35.015)
  line L29 (21.33, -37.515) -> (12.03, -28.215)
  line L30 (12.03, -37.515) -> (21.33, -28.215)
  line L31 (-14.18, -28.85) -> (-18.48, -28.85)
  line L32 (-11.68, -35.65) -> (-11.68, -31.35)
  line L33 (-18.48, -38.15) -> (-14.18, -38.15)
  line L34 (-20.98, -31.35) -> (-20.98, -35.65)
  line L35 (-11.68, -38.15) -> (-20.98, -28.85)
  line L36 (-20.98, -38.15) -> (-11.68, -28.85)
  arc A1 centre (46, -46) radius 1 clockwise from (47, -46) to (46, -47)
  arc A2 centre (46, 46) radius 1 clockwise from (46, 47) to (47, 46)
  arc A3 centre (-46, 46) radius 1 clockwise from (-47, 46) to (-46, 47)
  arc A4 centre (-46, -46) radius 1 clockwise from (-46, -47) to (-47, -46)
  circle C1 centre (16.68, -32.865) radius 1.65
  circle C2 centre (-16.33, -33.5) radius 1.65
  circle C3 centre (16.68, 32.54) radius 1.65
  circle C4 centre (-16.34, 32.54) radius 1.65
  circle C5 centre (16.68, -32.865) radius 4.65
  circle C6 centre (-16.33, -33.5) radius 4.65
  circle C7 centre (16.68, 32.54) radius 4.65
  circle C8 centre (-16.34, 32.54) radius 4.65
  circle C9 centre (16.68, 32.54) radius 2.675
  circle C10 centre (-16.34, 32.54) radius 2.675
  circle C11 centre (16.68, -32.865) radius 2.675
  circle C12 centre (-16.33, -33.5) radius 2.675
  arc A5 centre (18.83, 30.39) radius 2.5 clockwise from (21.33, 30.39) to (18.83, 27.89)
  arc A6 centre (14.53, 30.39) radius 2.5 clockwise from (14.53, 27.89) to (12.03, 30.39)
  arc A7 centre (18.83, 34.69) radius 2.5 clockwise from (18.83, 37.19) to (21.33, 34.69)
  arc A8 centre (14.53, 34.69) radius 2.5 clockwise from (12.03, 34.69) to (14.53, 37.19)
  arc A9 centre (-14.19, 30.39) radius 2.5 clockwise from (-11.69, 30.39) to (-14.19, 27.89)
  arc A10 centre (-14.19, 34.69) radius 2.5 clockwise from (-14.19, 37.19) to (-11.69, 34.69)
  arc A11 centre (-18.49, 34.69) radius 2.5 clockwise from (-20.99, 34.69) to (-18.49, 37.19)
  arc A12 centre (-18.49, 30.39) radius 2.5 clockwise from (-18.49, 27.89) to (-20.99, 30.39)
  arc A13 centre (18.83, -35.015) radius 2.5 clockwise from (21.33, -35.015) to (18.83, -37.515)
  arc A14 centre (18.83, -30.715) radius 2.5 clockwise from (18.83, -28.215) to (21.33, -30.715)
  arc A15 centre (14.53, -30.715) radius 2.5 clockwise from (12.03, -30.715) to (14.53, -28.215)
  arc A16 centre (14.53, -35.015) radius 2.5 clockwise from (14.53, -37.515) to (12.03, -35.015)
  arc A17 centre (-14.18, -35.65) radius 2.5 clockwise from (-11.68, -35.65) to (-14.18, -38.15)
  arc A18 centre (-14.18, -31.35) radius 2.5 clockwise from (-14.18, -28.85) to (-11.68, -31.35)
  arc A19 centre (-18.48, -31.35) radius 2.5 clockwise from (-20.98, -31.35) to (-18.48, -28.85)
  arc A20 centre (-18.48, -35.65) radius 2.5 clockwise from (-18.48, -38.15) to (-20.98, -35.65)
  point P38 (16.68, 32.54)
  point P24 (16.68, 32.54)
  point P37 (21.33, 27.89)
  point P36 (12.03, 27.89)
  point P34 (21.33, 37.19)
  point P35 (12.03, 37.19)
  point P55 (-16.34, 32.54)
  point P25 (-16.34, 32.54)
  point P53 (-11.69, 27.89)
  point P52 (-11.69, 37.19)
  point P51 (-20.99, 37.19)
  point P54 (-20.99, 27.89)
  point P72 (16.68, -32.865)
  point P32 (16.68, -32.865)
  point P70 (21.33, -37.515)
  point P69 (21.33, -28.215)
  point P68 (12.03, -28.215)
  point P71 (12.03, -37.515)
  point P89 (-16.33, -33.5)
  point P33 (-16.33, -33.5)
  point P87 (-11.68, -38.15)
  point P86 (-11.68, -28.85)
  point P85 (-20.98, -28.85)
  point P88 (-20.98, -38.15)
  concentric C3 C9
  concentric C4 C10
  concentric C1 C11
  concentric C2 C12
  horizontal L13
  perpendicular L13 L14
  parallel L13 L15
  parallel L14 L16
  coincident L17 P38
  coincident L18 P38
  coincident P24 P38
  coincident P37 L15
  coincident P37 L16
  tangent L15 A5
  tangent L16 A5
  coincident P36 L15
  coincident P36 L14
  tangent L15 A6
  tangent L14 A6
  equal A5 A6
  coincident P34 L16
  coincident P34 L13
  tangent L16 A7
  tangent L13 A7
  equal A5 A7
  coincident P35 L13
  coincident P35 L14
  tangent L13 A8
  tangent L14 A8
  equal A5 A8
  horizontal L19
  perpendicular L19 L20
  parallel L19 L21
  parallel L20 L22
  coincident L23 P55
  coincident L24 P55
  coincident P25 P55
  coincident P53 L21
  coincident P53 L20
  tangent L21 A9
  tangent L20 A9
  coincident P52 L20
  coincident P52 L19
  tangent L20 A10
  tangent L19 A10
  equal A9 A10
  coincident P51 L19
  coincident P51 L22
  tangent L19 A11
  tangent L22 A11
  equal A9 A11
  coincident P54 L21
  coincident P54 L22
  tangent L21 A12
  tangent L22 A12
  equal A9 A12
  horizontal L25
  perpendicular L25 L26
  parallel L25 L27
  parallel L26 L28
  coincident L29 P72
  coincident L30 P72
  coincident P32 P72
  coincident P70 L27
  coincident P70 L26
  tangent L27 A13
  tangent L26 A13
  coincident P69 L26
  coincident P69 L25
  tangent L26 A14
  tangent L25 A14
  equal A13 A14
  coincident P68 L25
  coincident P68 L28
  tangent L25 A15
  tangent L28 A15
  equal A13 A15
  coincident P71 L27
  coincident P71 L28
  tangent L27 A16
  tangent L28 A16
  equal A13 A16
  horizontal L31
  perpendicular L31 L32
  parallel L31 L33
  parallel L32 L34
  coincident L35 P89
  coincident L36 P89
  coincident P33 P89
  coincident P87 L33
  coincident P87 L32
  tangent L33 A17
  tangent L32 A17
  coincident P86 L32
  coincident P86 L31
  tangent L32 A18
  tangent L31 A18
  equal A17 A18
  coincident P85 L31
  coincident P85 L34
  tangent L31 A19
  tangent L34 A19
  equal A17 A19
  coincident P88 L33
  coincident P88 L34
  tangent L33 A20
  tangent L34 A20
  equal A17 A20
  dimension "d169" = 3
  dimension "d170" = 3
  dimension "d171" = 3
  dimension "d172" = 3
  dimension "d275" diameter C9 = 5.35
  dimension "d276" diameter C10 = 5.35
  dimension "d277" diameter C11 = 5.35
  dimension "d278" diameter C12 = 5.35
  dimension "d307" distance P36 P37 = 9.3
  dimension "d308" distance P35 P36 = 9.3
  dimension "d309" radius A5 = 2.5
  dimension "d310" distance P53 P54 = 9.3
  dimension "d311" distance P52 P53 = 9.3
  dimension "d312" radius A9 = 2.5
  dimension "d313" distance P70 P71 = 9.3
  dimension "d314" distance P69 P70 = 9.3
  dimension "d315" radius A13 = 2.5
  dimension "d316" distance P87 P88 = 9.3
  dimension "d317" distance P86 P87 = 9.3
  dimension "d318" radius A17 = 2.5
extrude "Extrude24" new body sketch "mounts" profile of C1 C2 C3 C4 C5 C6 C7 C8 along normal blind 19.2 bodies "upmount3", "upmount1", "upmount4", "upmount2"
component_insert "Component Insert5"
joint "Assemble1" alignAngle 0 alignOffsetX 0 alignOffsetY 0 alignOffsetZ 0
